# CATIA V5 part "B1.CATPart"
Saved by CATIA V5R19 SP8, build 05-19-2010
Part number: B1
Publications: "Li", "La", "e", "r"
Bounding box of the stored display mesh (mm): x -14.809 to 164.809, y -5 to 5, z -14.867 to 14.867
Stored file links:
  C:\Users\ThinkMotion\Desktop\EU_thinkMotion\iao\IAO_MMS_Groupe3\evulliez\evulliez\evulliez\Mecanisme\B1.CATPart
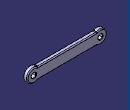
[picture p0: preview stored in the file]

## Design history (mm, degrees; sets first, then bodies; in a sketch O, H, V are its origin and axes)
Parameters
  Li = 150 mm
  La = 25 mm
  e = 10 mm
  r = 5 mm
Body1 (main body)
  Point1: (0, 0, 0)
  Line1: type PtDir, RefPoint Point1, Direction (1, 0, 0), Start 0, End 150 {= Li}
  Line2: type PtDir, RefPoint Point1, Direction (0, 1, 0), Start -5, End 5 {= e /2}
  Line3: type PtDir, RefPoint vertex of Line1, Direction (0, 1, 0), Start -5, End 5 {= e /2}
  Sketch1 on zx-plane, origin (0, 0, 0), H (-1, 0, 0), V (0, 0, 1)
    line L1 (-141.7084, -12.5) -> (-8.2916, -12.5)
    point P1 (-141.7084, -12.5)
    point P2 (-8.2916, -12.5)
    line L2 (-141.7084, 12.5) -> (-8.2916, 12.5)
    point P3 (-141.7084, 12.5)
    point P4 (-8.2916, 12.5)
    arc A1 centre (0, 0) radius 15 from (-8.2916, -12.5) to (-8.2916, 12.5) ccw
    point P5 (0, 0)
    point P6 (-8.2916, -12.5)
    point P7 (-8.2916, 12.5)
    reference projected point E1 (0, 0) from Point1
    reference projected point E2 (15, 0) from vertex [element of Sketch2 | element of Sketch2]
    reference projected line E3 (0, 0) -> (-150, 0) from Line1
    arc A2 centre (-150, 0) radius 15 from (-141.7084, 12.5) to (-141.7084, -12.5) ccw
    point P8 (-150, 0)
    point P9 (-141.7084, 12.5)
    point P10 (-141.7084, -12.5)
    reference projected point E4 (-150, 0) from vertex of Line1
    reference projected point E5 (-165, 0) from vertex [element of Sketch2 | element of Sketch2]
    distance L2 L1 = 25 {= La}
    distance E3 L2 = 12.5 {= La /2}
    horizontal: L1 H, L2 H
    coincidence: P5 E1, A1 E2, P7 P4, P6 P2, P8 E4, E5 A2, P9 P3, P10 P1
  Sketch2 on xy-plane, origin (0, 0, 0), H (1, 0, 0), V (0, 1, 0)
    line L1 (165, -5) -> (165, 5)
    line L2 (-15, 5) -> (-15, -5)
    point P2 (165, -5)
    point P4 (-15, 5)
    reference projected line E1 (150, -5) -> (150, 5) from Line3
    reference projected line E2 (0, -5) -> (0, 5) from Line2
    line L3 (165, 5) -> (-15, 5)
    point P5 (-15, 5)
    reference projected point E3 (150, 5) from vertex of Line3
    line L4 (-15, -5) -> (165, -5)
    point P6 (165, -5)
    reference projected point E4 (0, -5) from vertex of Line2
    distance E1 L1 = 15 {= r +10mm}
    distance E2 L2 = 15 {= r +10mm}
    vertical: L1 V, L2 V
    horizontal: L3 H, L4 H
    coincidence: E3 L3, E4 L4, P4 P5, P6 P2
  SolidCombine1: FirstComponentProfile Sketch1, FirstComponentDirection Sketch1, SecondComponentProfile Sketch2, SecondComponentDirection Sketch2
  Sketch3 on face of SolidCombine1 from Sketch2.L3, origin (0, 5, 0), H (1, 0, 0), V (0, 0, -1)
    point P1 (0, 0)
    reference projected point E1 (0, 0) from vertex of Line2
    coincidence: E1 P1
  Hole1: placed by Sketch3, at (0, 5, 0) direction (0, -1, 0), diameter 10 {= r *2}, through (limit type 3)
  Sketch4 on face of SolidCombine1 from Sketch2.L3, origin (150, 5, 0), H (1, 0, 0), V (0, 0, -1)
    point P1 (0, 0)
    reference projected point E1 (0, 0) from vertex of Line3
    coincidence: E1 P1
  Hole2: placed by Sketch4, at (150, 5, 0) direction (0, -1, 0), diameter 10 {= r *2}, through (limit type 3)
  Fillet1: radius 1, on edge [face of SolidCombine1 from Sketch2.L3 | face of Hole1]; edge [face of SolidCombine1 from Sketch2.L3 | face of Hole2]; edge [face of SolidCombine1 from Sketch2.L4 | face of Hole2]; edge [face of SolidCombine1 from Sketch2.L4 | face of Hole1]
  Fillet2: radius 2, on edge [face of SolidCombine1 from Sketch1.A2 | face of SolidCombine1 from Sketch2.L4]; edge [face of SolidCombine1 from Sketch1.A2 | face of SolidCombine1 from Sketch2.L3]; edge [face of SolidCombine1 from Sketch1.A1 | face of SolidCombine1 from Sketch2.L3]; edge [face of SolidCombine1 from Sketch1.A1 | face of SolidCombine1 from Sketch2.L4]; edge [face of SolidCombine1 from Sketch2.L3 | face of SolidCombine1 from Sketch1.L2]; edge [face of SolidCombine1 from Sketch1.L2 | face of SolidCombine1 from Sketch2.L4]; edge [face of SolidCombine1 from Sketch1.L1 | face of SolidCombine1 from Sketch2.L3]; edge [face of SolidCombine1 from Sketch2.L4 | face of SolidCombine1 from Sketch1.L1]
  Fillet3: radius 5, on edge [face of SolidCombine1 from Sketch1.L2 | face of SolidCombine1 from Sketch1.A1]; edge [face of SolidCombine1 from Sketch1.A2 | face of SolidCombine1 from Sketch1.L2]; edge [face of SolidCombine1 from Sketch1.A1 | face of SolidCombine1 from Sketch1.L1]; edge [face of SolidCombine1 from Sketch1.L1 | face of SolidCombine1 from Sketch1.A2]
